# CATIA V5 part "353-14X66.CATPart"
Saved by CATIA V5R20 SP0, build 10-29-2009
Part number: 353-14X66
Definition: NONE
Nomenclature: 353-14X66
Source: Unknown
Description: 353-14X66
Bounding box of the stored display mesh (mm): x -5 to 61, y -12 to 12, z -12 to 12
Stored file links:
  C:\Users\Utente\Desktop\IO LAVORO\3D X SITO CF\X SITO\PLASTICA\353\353-14X66.CATPart
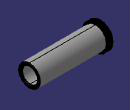
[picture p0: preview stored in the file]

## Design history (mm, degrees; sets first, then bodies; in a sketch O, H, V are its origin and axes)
Body1 "353-14X66" (main body)
  Solid1: solid without history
